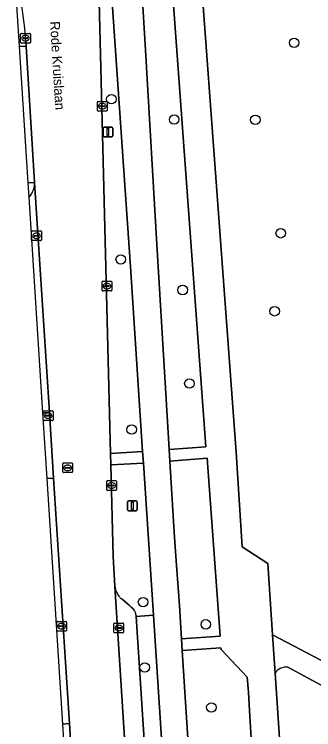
# Model space of a CAD drawing. Extents: x 160732 to 162107, y 387428 to 388479.
# Drawn here: x 160733.7 to 160764.5, y 388229.7 to 388303.3 of the extents above; entities that cross this region are included whole.
import ezdxf

# ---------------------------------------------------------------- set-up
doc = ezdxf.new("R2010")
doc.units = 0
for name, color, linetype in [('IMGEO_Boom', 7, 'Continuous'), ('IMGEO_Fietspad_gesloten', 7, 'Continuous'), ('IMGEO_Groenvoorziening', 7, 'Continuous'), ('IMGEO_Kolk', 7, 'Continuous'), ('IMGEO_Lichtmast', 7, 'Continuous'), ('IMGEO_Openbare_ruimte_label', 7, 'Continuous'), ('IMGEO_Parkeervlak_open', 7, 'Continuous'), ('IMGEO_Rijbaan_lokaal_gesloten', 7, 'Continuous'), ('IMGEO_Rioolput', 7, 'Continuous'), ('IMGEO_Voetpad_gesloten', 7, 'Continuous'), ('IMGEO_Voetpad_open', 7, 'Continuous')]:
    doc.layers.add(name, color=color, linetype=linetype)

msp = doc.modelspace()

# ---------------------------------------------------------------- linework, layer by layer
at = {"layer": 'IMGEO_Boom'}
for centre in [(160762.492, 388300.381), (160743.7, 388294.577), (160750.157, 388292.478), (160758.507, 388292.454), (160761.116, 388280.776), (160744.665, 388278.079), (160751.03, 388274.939), (160760.492, 388272.748), (160751.724, 388265.314), (160745.788, 388260.579), (160746.959, 388242.817), (160753.409, 388240.525), (160747.129, 388236.092), (160753.985, 388231.978)]:
    msp.add_circle(centre, 0.489, dxfattribs=at)
at = {"layer": 'IMGEO_Fietspad_gesloten'}
for points in [[(160747.195, 388299.608), (160746.444, 388312.149), (160746.207, 388317.446), (160746.457, 388319.607), (160746.692, 388321.756), (160743.926, 388321.849), (160743.893, 388321.676)], [(160743.788, 388304.535), (160745.672, 388277.306), (160746.918, 388258.316), (160746.997, 388257.111), (160748.024, 388241.464), (160748.889, 388228.277), (160749.048, 388225.849), (160749.131, 388224.59), (160750.242, 388207.176), (160750.395, 388204.771), (160751.507, 388187.342), (160751.656, 388185.005), (160752.882, 388165.791)], [(160757.321, 388139.646), (160754.959, 388176.292), (160754.882, 388177.484), (160752.889, 388208.407), (160752.811, 388209.62), (160750.992, 388237.833), (160750.915, 388239.028), (160750.693, 388242.474), (160750.397, 388246.597), (160750.293, 388248.039), (160750.172, 388250), (160749.72, 388257.312), (160749.645, 388258.525), (160749.431, 388261.982), (160748.363, 388279.605), (160747.195, 388299.608)]]:
    msp.add_lwpolyline(points, dxfattribs=at)
at = {"layer": 'IMGEO_Groenvoorziening'}
for points in [[(160743.072, 388324.909), (160743.059, 388324.793), (160742.517, 388317.918), (160742.354, 388314.126), (160742.318, 388310.124), (160743.627, 388258.106), (160746.918, 388258.316), (160745.672, 388277.306)], [(160746.692, 388321.756), (160746.457, 388319.607), (160746.207, 388317.446), (160746.444, 388312.149), (160747.195, 388299.608), (160748.363, 388279.605), (160749.431, 388261.982), (160749.645, 388258.525), (160753.429, 388258.806), (160749.247, 388316.021), (160748.996, 388319.272), (160748.948, 388319.898)], [(160769.515, 388307.073), (160769.758, 388317.535), (160767.675, 388317.521), (160763.897, 388317.505), (160763.922, 388319.595), (160755.985, 388319.522), (160752.017, 388319.486), (160756.525, 388258.235), (160757.159, 388248.492), (160759.795, 388246.8), (160760.285, 388239.445), (160765.972, 388236.463), (160767.186, 388237.86), (160768.163, 388238.698), (160770.116, 388239.927), (160775.533, 388242.124), (160775.347, 388242.444), (160773.518, 388245.587)], [(160733.72, 388308.033), (160734.232, 388300.001), (160734.925, 388300.041), (160734.87, 388300.85)], [(160745.672, 388277.306), (160743.788, 388304.535)], [(160735.81, 388286.005), (160735.127, 388285.961)], [(160735.127, 388285.961), (160735.221, 388284.487), (160735.42, 388284.736)], [(160746.997, 388257.111), (160743.657, 388256.931), (160743.893, 388247.559), (160744.062, 388244.426)], [(160746.23, 388241.519), (160746.235, 388241.444), (160746.241, 388241.35), (160748.024, 388241.464), (160746.997, 388257.111)], [(160744.682, 388243.203), (160744.798, 388243.105), (160745.516, 388242.498), (160745.745, 388242.304), (160745.859, 388242.208), (160745.952, 388242.119), (160746.058, 388241.981)], [(160776.812, 388211.908), (160778.801, 388215.713), (160781.176, 388219.288), (160783.913, 388222.596), (160785, 388223.715), (160773.267, 388229.959), (160761.855, 388236.107)], [(160760.548, 388235.506), (160764.386, 388177.9), (160772.941, 388178.536), (160772.784, 388193.329), (160773.361, 388199.548), (160774.077, 388203.781), (160775.231, 388207.916), (160776.812, 388211.908)]]:
    msp.add_lwpolyline(points, dxfattribs=at)
for points in [[(160753.54, 388257.631), (160749.72, 388257.312), (160750.172, 388250), (160750.293, 388248.039), (160750.397, 388246.597), (160750.693, 388242.474), (160750.915, 388239.028), (160754.889, 388239.306)], [(160757.802, 388233.55), (160757.654, 388235.08), (160754.982, 388237.925), (160754.963, 388238.121), (160750.992, 388237.833), (160752.811, 388209.62), (160759.203, 388210.036), (160758.884, 388215.157), (160757.913, 388231.668)]]:
    msp.add_lwpolyline(points, close=True, dxfattribs=at)
for centre, radius, start, end in [((160707.576, 388299.368), 27.334, 3.10817, 11.77498), ((160733.843, 388285.915), 1.969, 323.21919, 2.61343), ((160745.844, 388244.642), 1.795, 186.90725, 193.00438), ((160746.066, 388244.678), 2.019, 192.59084, 196.93439), ((160745.822, 388244.598), 1.762, 196.73621, 201.59028), ((160745.793, 388244.556), 1.72, 200.64467, 208.63865), ((160746.062, 388244.662), 2.008, 207.61344, 214.47754), ((160746.285, 388244.839), 2.292, 214.974, 221.10407), ((160745.782, 388244.384), 1.614, 220.69037, 227.04527), ((160745.228, 388241.425), 0.999, 26.41375, 33.84433), ((160745.407, 388241.493), 0.809, 19.59596, 27.72003), ((160745.001, 388241.338), 1.243, 13.67857, 20.03823), ((160745.184, 388241.383), 1.055, 7.40566, 13.64992), ((160761.659, 388234.812), 1.31, 81.38153, 148.00741)]:
    msp.add_arc(centre, radius, start, end, dxfattribs=at)
at = {"layer": 'IMGEO_Kolk'}
for p, q in [((160734.369, 388300.424), (160734.369, 388301.276)), ((160734.444, 388301.35), (160735.296, 388301.35)), ((160734.857, 388301.13), (160734.882, 388301.13)), ((160735.37, 388301.276), (160735.37, 388300.424)), ((160735.296, 388300.35), (160734.444, 388300.35)), ((160734.628, 388300.844), (160734.628, 388300.856)), ((160735.066, 388300.807), (160734.668, 388300.807)), ((160734.671, 388300.893), (160735.069, 388300.893)), ((160734.88, 388300.57), (160734.855, 388300.57)), ((160735.112, 388300.856), (160735.112, 388300.844)), ((160742.26, 388293.424), (160742.26, 388294.276)), ((160742.335, 388294.35), (160743.187, 388294.35)), ((160742.519, 388293.844), (160742.519, 388293.856)), ((160742.957, 388293.807), (160742.559, 388293.807)), ((160742.562, 388293.893), (160742.96, 388293.893)), ((160742.748, 388294.13), (160742.773, 388294.13)), ((160743.003, 388293.856), (160743.003, 388293.844)), ((160743.261, 388294.276), (160743.261, 388293.424)), ((160743.187, 388293.35), (160742.335, 388293.35)), ((160742.771, 388293.57), (160742.746, 388293.57)), ((160735.498, 388280.095), (160735.498, 388280.947)), ((160735.573, 388281.021), (160736.425, 388281.021)), ((160735.757, 388280.515), (160735.757, 388280.527)), ((160736.195, 388280.478), (160735.797, 388280.478)), ((160735.8, 388280.564), (160736.198, 388280.564)), ((160735.986, 388280.801), (160736.011, 388280.801)), ((160736.241, 388280.527), (160736.241, 388280.515)), ((160736.499, 388280.947), (160736.499, 388280.095)), ((160736.425, 388280.021), (160735.573, 388280.021)), ((160736.009, 388280.241), (160735.984, 388280.241)), ((160742.74, 388274.915), (160742.74, 388275.767)), ((160742.815, 388275.841), (160743.667, 388275.841)), ((160742.999, 388275.335), (160742.999, 388275.347)), ((160743.042, 388275.384), (160743.44, 388275.384)), ((160743.228, 388275.621), (160743.253, 388275.621)), ((160743.483, 388275.347), (160743.483, 388275.335)), ((160743.741, 388275.767), (160743.741, 388274.915)), ((160743.667, 388274.841), (160742.815, 388274.841)), ((160743.437, 388275.298), (160743.039, 388275.298)), ((160743.251, 388275.061), (160743.226, 388275.061)), ((160736.701, 388261.576), (160736.701, 388262.428)), ((160736.776, 388262.502), (160737.628, 388262.502)), ((160737.189, 388262.282), (160737.214, 388262.282)), ((160737.702, 388262.428), (160737.702, 388261.576)), ((160737.628, 388261.502), (160736.776, 388261.502)), ((160736.96, 388261.996), (160736.96, 388262.008)), ((160737.398, 388261.959), (160737, 388261.959)), ((160737.003, 388262.045), (160737.401, 388262.045)), ((160737.212, 388261.722), (160737.187, 388261.722)), ((160737.444, 388262.008), (160737.444, 388261.996)), ((160743.225, 388254.39), (160743.225, 388255.242)), ((160743.3, 388255.316), (160744.152, 388255.316)), ((160743.484, 388254.81), (160743.484, 388254.822)), ((160743.922, 388254.773), (160743.524, 388254.773)), ((160743.527, 388254.859), (160743.925, 388254.859)), ((160743.713, 388255.096), (160743.738, 388255.096)), ((160743.968, 388254.822), (160743.968, 388254.81)), ((160744.226, 388255.242), (160744.226, 388254.39)), ((160744.152, 388254.316), (160743.3, 388254.316)), ((160743.736, 388254.536), (160743.711, 388254.536)), ((160738.087, 388239.907), (160738.087, 388240.759)), ((160738.162, 388240.833), (160739.014, 388240.833)), ((160739.088, 388240.759), (160739.088, 388239.907)), ((160738.346, 388240.327), (160738.346, 388240.339)), ((160738.784, 388240.29), (160738.386, 388240.29)), ((160738.389, 388240.376), (160738.787, 388240.376)), ((160738.598, 388240.053), (160738.573, 388240.053)), ((160738.575, 388240.613), (160738.6, 388240.613)), ((160738.83, 388240.339), (160738.83, 388240.327)), ((160743.963, 388239.73), (160743.963, 388240.582)), ((160744.038, 388240.656), (160744.89, 388240.656)), ((160744.222, 388240.15), (160744.222, 388240.162)), ((160744.66, 388240.113), (160744.262, 388240.113)), ((160744.265, 388240.199), (160744.663, 388240.199)), ((160744.451, 388240.436), (160744.476, 388240.436)), ((160744.706, 388240.162), (160744.706, 388240.15)), ((160744.964, 388240.582), (160744.964, 388239.73)), ((160739.014, 388239.833), (160738.162, 388239.833)), ((160744.89, 388239.656), (160744.038, 388239.656)), ((160744.474, 388239.876), (160744.449, 388239.876))]:
    msp.add_line(p, q, dxfattribs=at)
for points in [[(160734.369, 388300.424), (160734.369, 388301.276)], [(160734.444, 388301.35), (160735.296, 388301.35)], [(160735.37, 388301.276), (160735.37, 388300.424)], [(160735.296, 388300.35), (160734.444, 388300.35)], [(160742.26, 388293.424), (160742.26, 388294.276)], [(160742.335, 388294.35), (160743.187, 388294.35)], [(160743.261, 388294.276), (160743.261, 388293.424)], [(160743.187, 388293.35), (160742.335, 388293.35)], [(160735.498, 388280.095), (160735.498, 388280.947)], [(160735.573, 388281.021), (160736.425, 388281.021)], [(160736.499, 388280.947), (160736.499, 388280.095)], [(160736.425, 388280.021), (160735.573, 388280.021)], [(160742.74, 388274.915), (160742.74, 388275.767)], [(160742.815, 388275.841), (160743.667, 388275.841)], [(160743.741, 388275.767), (160743.741, 388274.915)], [(160743.667, 388274.841), (160742.815, 388274.841)], [(160736.701, 388261.576), (160736.701, 388262.428)], [(160736.776, 388262.502), (160737.628, 388262.502)], [(160737.702, 388262.428), (160737.702, 388261.576)], [(160737.628, 388261.502), (160736.776, 388261.502)], [(160743.225, 388254.39), (160743.225, 388255.242)], [(160743.3, 388255.316), (160744.152, 388255.316)], [(160744.226, 388255.242), (160744.226, 388254.39)], [(160744.152, 388254.316), (160743.3, 388254.316)], [(160738.087, 388239.907), (160738.087, 388240.759)], [(160738.162, 388240.833), (160739.014, 388240.833)], [(160739.088, 388240.759), (160739.088, 388239.907)], [(160743.963, 388239.73), (160743.963, 388240.582)], [(160744.038, 388240.656), (160744.89, 388240.656)], [(160744.964, 388240.582), (160744.964, 388239.73)], [(160739.014, 388239.833), (160738.162, 388239.833)], [(160744.89, 388239.656), (160744.038, 388239.656)]]:
    msp.add_lwpolyline(points, dxfattribs=at)
for centre, radius, start, end in [((160734.446, 388301.274), 0.0765, 91.55205, 178.44795), ((160734.446, 388301.274), 0.0765, 91.55205, 178.44795), ((160735.294, 388301.274), 0.0765, 1.55205, 88.44795), ((160735.294, 388301.274), 0.0765, 1.55205, 88.44795), ((160734.446, 388300.426), 0.0765, 181.55205, 268.44795), ((160734.446, 388300.426), 0.0765, 181.55205, 268.44795), ((160734.668, 388300.853), 0.0403, 85.87752, 175.75265), ((160734.665, 388300.843), 0.0366, 178.93798, 274.71019), ((160735.069, 388300.85), 0.043, 264.86636, 352.45326), ((160735.073, 388300.855), 0.0386, 1.73085, 96.63898), ((160735.294, 388300.426), 0.0765, 271.55205, 358.44795), ((160735.294, 388300.426), 0.0765, 271.55205, 358.44795), ((160742.337, 388294.274), 0.0765, 91.55205, 178.44795), ((160742.337, 388294.274), 0.0765, 91.55205, 178.44795), ((160742.559, 388293.853), 0.0403, 85.87752, 175.75265), ((160742.556, 388293.843), 0.0366, 178.93798, 274.71019), ((160742.96, 388293.85), 0.043, 264.86636, 352.45326), ((160742.964, 388293.855), 0.0386, 1.73085, 96.63898), ((160743.185, 388294.274), 0.0765, 1.55205, 88.44795), ((160743.185, 388294.274), 0.0765, 1.55205, 88.44795), ((160742.337, 388293.426), 0.0765, 181.55205, 268.44795), ((160742.337, 388293.426), 0.0765, 181.55205, 268.44795), ((160743.185, 388293.426), 0.0765, 271.55205, 358.44795), ((160743.185, 388293.426), 0.0765, 271.55205, 358.44795), ((160735.575, 388280.945), 0.0765, 91.55205, 178.44795), ((160735.575, 388280.945), 0.0765, 91.55205, 178.44795), ((160735.797, 388280.524), 0.0403, 85.87752, 175.75265), ((160735.794, 388280.514), 0.0366, 178.93798, 274.71019), ((160736.198, 388280.521), 0.043, 264.86636, 352.45326), ((160736.202, 388280.526), 0.0386, 1.73085, 96.63898), ((160736.423, 388280.945), 0.0765, 1.55205, 88.44795), ((160736.423, 388280.945), 0.0765, 1.55205, 88.44795), ((160735.575, 388280.097), 0.0765, 181.55205, 268.44795), ((160735.575, 388280.097), 0.0765, 181.55205, 268.44795), ((160736.423, 388280.097), 0.0765, 271.55205, 358.44795), ((160736.423, 388280.097), 0.0765, 271.55205, 358.44795), ((160742.817, 388275.765), 0.0765, 91.55205, 178.44795), ((160742.817, 388275.765), 0.0765, 91.55205, 178.44795), ((160743.039, 388275.344), 0.0403, 85.87752, 175.75265), ((160743.036, 388275.334), 0.0366, 178.93798, 274.71019), ((160743.44, 388275.341), 0.043, 264.86636, 352.45326), ((160743.444, 388275.346), 0.0386, 1.73085, 96.63898), ((160743.665, 388275.765), 0.0765, 1.55205, 88.44795), ((160743.665, 388275.765), 0.0765, 1.55205, 88.44795), ((160742.817, 388274.917), 0.0765, 181.55205, 268.44795), ((160742.817, 388274.917), 0.0765, 181.55205, 268.44795), ((160743.665, 388274.917), 0.0765, 271.55205, 358.44795), ((160743.665, 388274.917), 0.0765, 271.55205, 358.44795), ((160736.778, 388262.426), 0.0765, 91.55205, 178.44795), ((160736.778, 388262.426), 0.0765, 91.55205, 178.44795), ((160737.626, 388262.426), 0.0765, 1.55205, 88.44795), ((160737.626, 388262.426), 0.0765, 1.55205, 88.44795), ((160736.778, 388261.578), 0.0765, 181.55205, 268.44795), ((160736.778, 388261.578), 0.0765, 181.55205, 268.44795), ((160737, 388262.005), 0.0403, 85.87752, 175.75265), ((160736.997, 388261.995), 0.0366, 178.93798, 274.71019), ((160737.401, 388262.002), 0.043, 264.86636, 352.45326), ((160737.405, 388262.007), 0.0386, 1.73085, 96.63898), ((160737.626, 388261.578), 0.0765, 271.55205, 358.44795), ((160737.626, 388261.578), 0.0765, 271.55205, 358.44795), ((160743.302, 388255.24), 0.0765, 91.55205, 178.44795), ((160743.302, 388255.24), 0.0765, 91.55205, 178.44795), ((160743.524, 388254.819), 0.0403, 85.87752, 175.75265), ((160743.521, 388254.809), 0.0366, 178.93798, 274.71019), ((160743.925, 388254.816), 0.043, 264.86636, 352.45326), ((160743.929, 388254.821), 0.0386, 1.73085, 96.63898), ((160744.15, 388255.24), 0.0765, 1.55205, 88.44795), ((160744.15, 388255.24), 0.0765, 1.55205, 88.44795), ((160743.302, 388254.392), 0.0765, 181.55205, 268.44795), ((160743.302, 388254.392), 0.0765, 181.55205, 268.44795), ((160744.15, 388254.392), 0.0765, 271.55205, 358.44795), ((160744.15, 388254.392), 0.0765, 271.55205, 358.44795), ((160738.164, 388240.757), 0.0765, 91.55205, 178.44795), ((160738.164, 388240.757), 0.0765, 91.55205, 178.44795), ((160739.012, 388240.757), 0.0765, 1.55205, 88.44795), ((160739.012, 388240.757), 0.0765, 1.55205, 88.44795), ((160738.386, 388240.336), 0.0403, 85.87752, 175.75265), ((160738.383, 388240.326), 0.0366, 178.93798, 274.71019), ((160738.787, 388240.333), 0.043, 264.86636, 352.45326), ((160738.791, 388240.338), 0.0386, 1.73085, 96.63898), ((160744.04, 388240.58), 0.0765, 91.55205, 178.44795), ((160744.04, 388240.58), 0.0765, 91.55205, 178.44795), ((160744.262, 388240.159), 0.0403, 85.87752, 175.75265), ((160744.259, 388240.149), 0.0366, 178.93798, 274.71019), ((160744.663, 388240.156), 0.043, 264.86636, 352.45326), ((160744.667, 388240.161), 0.0386, 1.73085, 96.63898), ((160744.888, 388240.58), 0.0765, 1.55205, 88.44795), ((160744.888, 388240.58), 0.0765, 1.55205, 88.44795), ((160738.164, 388239.909), 0.0765, 181.55205, 268.44795), ((160738.164, 388239.909), 0.0765, 181.55205, 268.44795), ((160739.012, 388239.909), 0.0765, 271.55205, 358.44795), ((160739.012, 388239.909), 0.0765, 271.55205, 358.44795), ((160744.04, 388239.732), 0.0765, 181.55205, 268.44795), ((160744.04, 388239.732), 0.0765, 181.55205, 268.44795), ((160744.888, 388239.732), 0.0765, 271.55205, 358.44795), ((160744.888, 388239.732), 0.0765, 271.55205, 358.44795)]:
    msp.add_arc(centre, radius, start, end, dxfattribs=at)
for centre, major_axis, ratio, start_param, end_param in [((160734.856, 388300.85), (-0.387, 0.002), 0.722429, 4.712389, 7.853982), ((160734.881, 388300.85), (-0.39, 0.002), 0.717154, 1.570796, 4.712389), ((160742.747, 388293.85), (-0.387, 0.002), 0.722429, 4.712389, 7.853982), ((160742.772, 388293.85), (-0.39, 0.002), 0.717154, 1.570796, 4.712389), ((160735.985, 388280.521), (-0.387, 0.002), 0.722429, 4.712389, 7.853982), ((160736.01, 388280.521), (-0.39, 0.002), 0.717154, 1.570796, 4.712389), ((160743.227, 388275.341), (-0.387, 0.002), 0.722429, 4.712389, 7.853982), ((160743.252, 388275.341), (-0.39, 0.002), 0.717154, 1.570796, 4.712389), ((160737.188, 388262.002), (-0.387, 0.002), 0.722429, 4.712389, 7.853982), ((160737.213, 388262.002), (-0.39, 0.002), 0.717154, 1.570796, 4.712389), ((160743.712, 388254.816), (-0.387, 0.002), 0.722429, 4.712389, 7.853982), ((160743.737, 388254.816), (-0.39, 0.002), 0.717154, 1.570796, 4.712389), ((160738.574, 388240.333), (-0.387, 0.002), 0.722429, 4.712389, 7.853982), ((160738.599, 388240.333), (-0.39, 0.002), 0.717154, 1.570796, 4.712389), ((160744.45, 388240.156), (-0.387, 0.002), 0.722429, 4.712389, 7.853982), ((160744.475, 388240.156), (-0.39, 0.002), 0.717154, 1.570796, 4.712389)]:
    msp.add_ellipse(centre, major_axis=major_axis, ratio=ratio, start_param=start_param, end_param=end_param, dxfattribs=at)
at = {"layer": 'IMGEO_Lichtmast'}
for p, q in [((160742.849, 388290.808), (160742.849, 388291.608)), ((160742.849, 388291.608), (160742.849, 388290.808)), ((160742.949, 388291.708), (160743.739, 388291.708)), ((160743.739, 388291.708), (160742.949, 388291.708)), ((160743.839, 388291.608), (160743.839, 388290.808)), ((160743.839, 388290.808), (160743.839, 388291.608)), ((160743.739, 388290.708), (160742.949, 388290.708)), ((160742.949, 388290.708), (160743.739, 388290.708)), ((160745.467, 388253.227), (160746.257, 388253.227)), ((160746.257, 388253.227), (160745.467, 388253.227)), ((160745.367, 388252.327), (160745.367, 388253.127)), ((160745.367, 388253.127), (160745.367, 388252.327)), ((160746.357, 388253.127), (160746.357, 388252.327)), ((160746.357, 388252.327), (160746.357, 388253.127)), ((160746.257, 388252.227), (160745.467, 388252.227)), ((160745.467, 388252.227), (160746.257, 388252.227))]:
    msp.add_line(p, q, dxfattribs=at)
for points in [[(160743.269, 388291.583), (160743.419, 388291.583), (160743.419, 388290.833), (160743.269, 388290.833), (160743.269, 388291.583)], [(160745.787, 388253.102), (160745.937, 388253.102), (160745.937, 388252.352), (160745.787, 388252.352), (160745.787, 388253.102)]]:
    msp.add_lwpolyline(points, dxfattribs=at)
for centre, start, end in [((160742.949, 388291.608), 90, 180), ((160742.949, 388291.608), 90, 180), ((160743.739, 388291.608), 0, 90), ((160743.739, 388291.608), 360, 90), ((160742.949, 388290.808), 180, 270), ((160742.949, 388290.808), 180, 270), ((160743.739, 388290.808), 270, 0), ((160743.739, 388290.808), 270, 0), ((160745.467, 388253.127), 90, 180), ((160745.467, 388253.127), 90, 180), ((160746.257, 388253.127), 0, 90), ((160746.257, 388253.127), 360, 90), ((160745.467, 388252.327), 180, 270), ((160745.467, 388252.327), 180, 270), ((160746.257, 388252.327), 270, 0), ((160746.257, 388252.327), 270, 0)]:
    msp.add_arc(centre, 0.1, start, end, dxfattribs=at)
at = {"layer": 'IMGEO_Parkeervlak_open'}
for points in [[(160736.635, 388262.297), (160736.636, 388262.297), (160737.327, 388262.341), (160735.81, 388286.005)], [(160735.42, 388284.736), (160735.221, 388284.487), (160736.635, 388262.297)], [(160744.062, 388244.426), (160748.09, 388181.039), (160748.734, 388171.139), (160754.378, 388083.355), (160754.541, 388082.023)], [(160746.058, 388241.981), (160745.952, 388242.119), (160745.859, 388242.208), (160745.745, 388242.304), (160745.516, 388242.498), (160744.798, 388243.105), (160744.682, 388243.203)], [(160747.244, 388225.708), (160747.091, 388228.103), (160746.241, 388241.35), (160746.235, 388241.444), (160746.23, 388241.519)]]:
    msp.add_lwpolyline(points, dxfattribs=at)
msp.add_lwpolyline([(160738.677, 388230.27), (160739.38, 388230.315), (160737.76, 388255.584), (160737.066, 388255.54)], close=True, dxfattribs=at)
for centre, radius, start, end in [((160733.843, 388285.915), 1.969, 323.21919, 2.61343), ((160745.844, 388244.642), 1.795, 186.90725, 193.00438), ((160746.066, 388244.678), 2.019, 192.59084, 196.93439), ((160745.822, 388244.598), 1.762, 196.73621, 201.59028), ((160745.793, 388244.556), 1.72, 200.64467, 208.63865), ((160746.062, 388244.662), 2.008, 207.61344, 214.47754), ((160746.285, 388244.839), 2.292, 214.974, 221.10407), ((160745.782, 388244.384), 1.614, 220.69037, 227.04527), ((160745.228, 388241.425), 0.999, 26.41375, 33.84433), ((160745.407, 388241.493), 0.809, 19.59596, 27.72003), ((160745.001, 388241.338), 1.243, 13.67857, 20.03823), ((160745.184, 388241.383), 1.055, 7.40566, 13.64992)]:
    msp.add_arc(centre, radius, start, end, dxfattribs=at)
at = {"layer": 'IMGEO_Rijbaan_lokaal_gesloten'}
for points in [[(160748.09, 388181.039), (160744.062, 388244.426), (160743.893, 388247.559), (160743.657, 388256.931), (160743.627, 388258.106), (160742.318, 388310.124), (160742.354, 388314.126), (160742.517, 388317.918), (160743.059, 388324.793), (160743.072, 388324.909), (160743.479, 388328.38), (160743.492, 388328.511), (160743.84, 388331.193), (160744.108, 388332.398), (160736.212, 388331.727), (160736.555, 388327.746), (160736.903, 388324.299), (160736.949, 388323.852)], [(160734.87, 388300.85), (160734.925, 388300.041), (160735.809, 388286.024), (160735.81, 388286.005), (160737.327, 388262.341), (160737.76, 388255.584), (160739.38, 388230.315), (160739.737, 388224.742)]]:
    msp.add_lwpolyline(points, dxfattribs=at)
msp.add_arc((160707.576, 388299.368), 27.334, 3.10817, 11.77498, dxfattribs=at)
at = {"layer": 'IMGEO_Rioolput'}
for p, q in [((160738.706, 388256.215), (160738.706, 388257.067)), ((160738.781, 388257.141), (160739.633, 388257.141)), ((160739.194, 388256.921), (160739.219, 388256.921)), ((160739.707, 388257.067), (160739.707, 388256.215)), ((160738.965, 388256.635), (160738.965, 388256.647)), ((160739.403, 388256.598), (160739.005, 388256.598)), ((160739.008, 388256.684), (160739.406, 388256.684)), ((160739.217, 388256.361), (160739.192, 388256.361)), ((160739.449, 388256.647), (160739.449, 388256.635)), ((160739.633, 388256.141), (160738.781, 388256.141))]:
    msp.add_line(p, q, dxfattribs=at)
for points in [[(160738.706, 388256.215), (160738.706, 388257.067)], [(160738.781, 388257.141), (160739.633, 388257.141)], [(160739.707, 388257.067), (160739.707, 388256.215)], [(160739.633, 388256.141), (160738.781, 388256.141)]]:
    msp.add_lwpolyline(points, dxfattribs=at)
for centre, radius, start, end in [((160738.783, 388257.065), 0.0765, 91.55205, 178.44795), ((160738.783, 388257.065), 0.0765, 91.55205, 178.44795), ((160739.631, 388257.065), 0.0765, 1.55205, 88.44795), ((160739.631, 388257.065), 0.0765, 1.55205, 88.44795), ((160738.783, 388256.217), 0.0765, 181.55205, 268.44795), ((160738.783, 388256.217), 0.0765, 181.55205, 268.44795), ((160739.005, 388256.644), 0.0403, 85.87752, 175.75265), ((160739.002, 388256.634), 0.0366, 178.93798, 274.71019), ((160739.406, 388256.641), 0.043, 264.86636, 352.45326), ((160739.41, 388256.646), 0.0386, 1.73085, 96.63898), ((160739.631, 388256.217), 0.0765, 271.55205, 358.44795), ((160739.631, 388256.217), 0.0765, 271.55205, 358.44795)]:
    msp.add_arc(centre, radius, start, end, dxfattribs=at)
for centre, major_axis, ratio, start_param, end_param in [((160739.193, 388256.641), (-0.387, 0.002), 0.722429, 4.712389, 7.853982), ((160739.218, 388256.641), (-0.39, 0.002), 0.717154, 1.570796, 4.712389)]:
    msp.add_ellipse(centre, major_axis=major_axis, ratio=ratio, start_param=start_param, end_param=end_param, dxfattribs=at)
at = {"layer": 'IMGEO_Voetpad_gesloten'}
for points in [[(160790.982, 388223.302), (160789.176, 388224.238), (160780.509, 388228.837), (160766.897, 388235.977), (160765.972, 388236.463), (160760.285, 388239.445), (160760.548, 388235.506)], [(160761.855, 388236.107), (160773.267, 388229.959), (160785, 388223.715), (160787.96, 388222.085)]]:
    msp.add_lwpolyline(points, dxfattribs=at)
msp.add_arc((160761.659, 388234.812), 1.31, 81.38153, 148.00741, dxfattribs=at)
at = {"layer": 'IMGEO_Voetpad_open'}
msp.add_lwpolyline([(160764.386, 388177.9), (160760.548, 388235.506), (160760.285, 388239.445), (160759.795, 388246.8), (160757.159, 388248.492), (160756.525, 388258.235), (160752.017, 388319.486), (160748.996, 388319.272), (160749.247, 388316.021), (160753.429, 388258.806), (160749.645, 388258.525), (160749.72, 388257.312), (160753.54, 388257.631), (160754.889, 388239.306), (160750.915, 388239.028), (160750.992, 388237.833), (160754.963, 388238.121), (160754.982, 388237.925), (160757.654, 388235.08), (160757.802, 388233.55), (160757.913, 388231.668), (160758.884, 388215.157)], dxfattribs=at)
for points in [[(160735.127, 388285.961), (160735.81, 388286.005), (160735.809, 388286.024), (160734.925, 388300.041), (160734.232, 388300.001)], [(160737.066, 388255.54), (160737.76, 388255.584), (160737.327, 388262.341), (160736.636, 388262.297), (160736.635, 388262.297)], [(160746.918, 388258.316), (160743.627, 388258.106), (160743.657, 388256.931), (160746.997, 388257.111)], [(160748.024, 388241.464), (160746.241, 388241.35), (160747.091, 388228.103), (160748.889, 388228.277)], [(160739.032, 388224.697), (160739.737, 388224.742), (160739.38, 388230.315), (160738.677, 388230.27)]]:
    msp.add_lwpolyline(points, close=True, dxfattribs=at)

# ---------------------------------------------------------------- texts
at = {"layer": 'IMGEO_Openbare_ruimte_label'}
msp.add_text('Rode Kruislaan', height=1, rotation=273.44049, dxfattribs=at).set_placement((160737.39, 388302.572))

doc.saveas('drawing.dxf')
